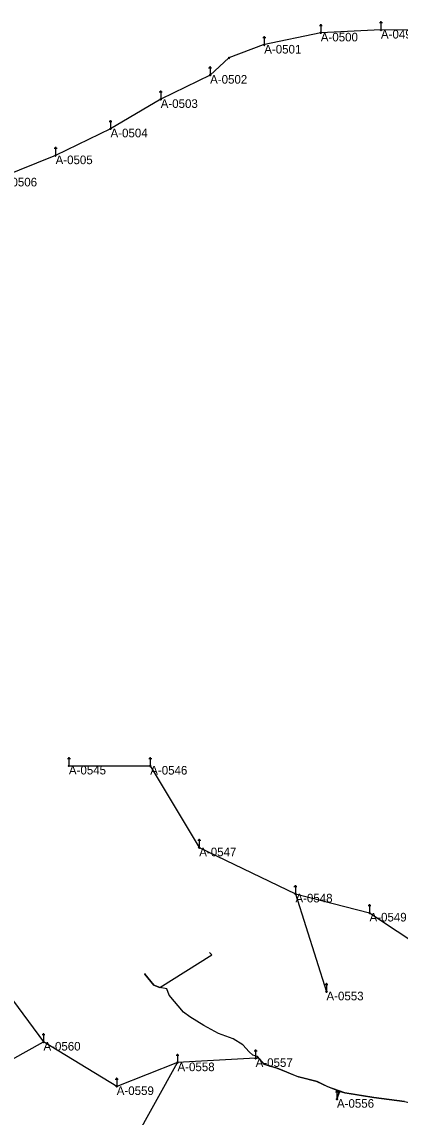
# Model space of a CAD drawing. Extents: x -729889 to -691139, y -995431 to -974354.
# Drawn here: x -725591.1 to -725459.3, y -977808.4 to -977426.9 of the extents above; entities that cross this region are included whole.
import ezdxf

# ---------------------------------------------------------------- set-up
doc = ezdxf.new("R2010")
doc.units = 0
for name, color, linetype in [('Atributy', 7, 'Continuous'), ('Kabel napájecí ze systému VO', 7, 'Continuous'), ('Kabelové vedení VO', 7, 'Continuous'), ('Spojka kabelová', 7, 'Continuous'), ('Světelný bod na stožáru sadovém', 7, 'Continuous')]:
    doc.layers.add(name, color=color, linetype=linetype)

# ---------------------------------------------------------------- blocks, each defined once
blk = doc.blocks.new('6.571')
at = {"layer": 'Světelný bod na stožáru sadovém'}
for p, q in [((-0.51, 2.54), (0.51, 2.54)), ((0, 2.54), (0, 0.2))]:
    blk.add_line(p, q, dxfattribs=at)
for points in [[(0.25, 2.54), (0.25, 2.56), (0.25, 2.58), (0.24, 2.6), (0.24, 2.62), (0.23, 2.64), (0.22, 2.66), (0.21, 2.69), (0.19, 2.7), (0.18, 2.72), (0.16, 2.73), (0.15, 2.75), (0.13, 2.76), (0.11, 2.77), (0.09, 2.78), (0.07, 2.78), (0.05, 2.79), (0.02, 2.79), (0, 2.79), (-0.02, 2.79), (-0.05, 2.79), (-0.07, 2.78), (-0.09, 2.78), (-0.11, 2.77), (-0.13, 2.76), (-0.15, 2.75), (-0.16, 2.73), (-0.18, 2.72), (-0.19, 2.7), (-0.21, 2.69), (-0.22, 2.66), (-0.23, 2.64), (-0.24, 2.62), (-0.24, 2.6), (-0.25, 2.58), (-0.25, 2.56), (-0.25, 2.54)], [(-0.2, 0), (-0.17, -0.1), (-0.08, -0.18), (0.04, -0.19), (0.13, -0.14), (0.19, -0.05), (0.18, 0.07), (0.12, 0.15), (0.02, 0.19), (-0.09, 0.17), (-0.17, 0.09), (-0.18, -0.01), (-0.15, -0.1), (-0.06, -0.17), (0.04, -0.17), (0.12, -0.12), (0.17, -0.03), (0.16, 0.08), (0.1, 0.14), (0.01, 0.17), (-0.09, 0.14), (-0.15, 0.07), (-0.16, -0.01), (-0.12, -0.1), (-0.04, -0.15), (0.04, -0.15), (0.12, -0.1), (0.15, -0.01), (0.14, 0.07), (0.08, 0.13), (-0.01, 0.15), (-0.09, 0.12), (-0.13, 0.06), (-0.14, -0.02), (-0.1, -0.1), (-0.03, -0.13), (0.04, -0.13), (0.11, -0.08), (0.13, 0), (0.12, 0.07), (0.06, 0.12), (-0.02, 0.13), (-0.08, 0.1), (-0.12, 0.05), (-0.12, -0.03), (-0.08, -0.09), (-0.02, -0.11), (0.05, -0.11), (0.1, -0.06), (0.11, 0.01), (0.1, 0.06), (0.05, 0.11), (-0.02, 0.11), (-0.07, 0.09), (-0.1, 0.04), (-0.1, -0.03), (-0.06, -0.08), (-0.02, -0.1), (0.05, -0.08), (0.09, -0.04), (0.1, 0.01), (0.08, 0.06), (0.03, 0.09), (-0.02, 0.09), (-0.06, 0.07), (-0.08, 0.02), (-0.08, -0.03), (-0.05, -0.06), (-0.01, -0.08), (0.04, -0.06), (0.07, -0.03), (0.07, 0.01), (0.06, 0.05), (0.02, 0.07), (-0.02, 0.07), (-0.05, 0.05), (-0.07, 0.02), (-0.06, -0.03), (-0.04, -0.05), (0, -0.06), (0.04, -0.04), (0.05, -0.02), (0.06, 0.01), (0.04, 0.04), (0.01, 0.05), (-0.02, 0.05), (-0.04, 0.04), (-0.05, 0.01), (-0.04, -0.02), (-0.02, -0.03), (0.01, -0.04), (0.03, -0.03), (0.04, -0.01), (0.04, 0.01), (0.02, 0.03), (0.01, 0.04), (-0.01, 0.03), (-0.02, 0.02), (-0.03, 0.01), (-0.02, -0.01), (-0.01, -0.02)], [(-0.01, -0.02), (0.01, -0.02), (0.01, -0.01), (0.02, 0), (0.02, 0.01), (0.01, 0.02), (0, 0.02), (-0.01, 0.01), (-0.01, 0.01), (-0.01, 0.01)]]:
    blk.add_lwpolyline(points, dxfattribs=at)
blk.add_circle((0, 0), 0.203, dxfattribs=at)
blk = doc.blocks.new('4.0200_BB')
at = {"layer": 'Spojka kabelová'}
blk.add_lwpolyline([(-0.02, 0.01), (-0.02, 0.17), (-0.1, 0.17), (-0.1, 0.21), (-0.02, 0.21), (-0.02, 0.28), (0.02, 0.28), (0.02, 0.21), (0.11, 0.21), (0.11, 0.17), (0.02, 0.17), (0.02, 0.01)], close=True, dxfattribs=at)
for radius in [0.15, 0.0945]:
    blk.add_circle((0, -0.13), radius, dxfattribs=at)

msp = doc.modelspace()

# ---------------------------------------------------------------- linework, layer by layer
at = {"layer": 'Kabel napájecí ze systému VO'}
for points in [[(-725548.15, -977758.36), (-725548.27, -977758.56), (-725545.1, -977762.41), (-725543.07, -977763.16), (-725524.88, -977751.79), (-725525.78, -977751.08)], [(-725457.8, -977802.91), (-725468.45, -977801.52), (-725478.54, -977799.9), (-725484.47, -977797.77), (-725488.21, -977795.98), (-725495.24, -977794.21), (-725501.53, -977791.51), (-725506.66, -977789.93), (-725509.04, -977787.25), (-725510.58, -977786.74), (-725511.92, -977785.63), (-725514.13, -977783.15), (-725517.54, -977781.11), (-725522.57, -977779.26), (-725527.75, -977776.47), (-725532.59, -977773.41), (-725534.79, -977771.84), (-725539.83, -977765.9), (-725540.63, -977763.69), (-725543.07, -977763.16), (-725545.1, -977762.41), (-725548.27, -977758.56), (-725548.15, -977758.36)]]:
    msp.add_lwpolyline(points, dxfattribs=at)
at = {"layer": 'Kabelové vedení VO'}
for p, q in [((-725486.95, -977430.69), (-725507.02, -977434.9)), ((-725466, -977429.71), (-725486.95, -977430.69)), ((-725444.44, -977429.86), (-725466, -977429.71)), ((-725525.51, -977445.41), (-725542.73, -977453.86)), ((-725542.73, -977453.86), (-725560.21, -977464.1)), ((-725560.21, -977464.1), (-725579.35, -977473.45)), ((-725579.35, -977473.45), (-725598.73, -977481.2)), ((-725574.71, -977686), (-725546.38, -977686.05)), ((-725546.38, -977686.05), (-725529.3, -977714.5)), ((-725529.3, -977714.5), (-725495.79, -977730.57)), ((-725495.79, -977730.57), (-725484.98, -977764.67)), ((-725495.79, -977730.57), (-725469.98, -977737.21)), ((-725469.98, -977737.21), (-725447.77, -977751.93)), ((-725609.81, -977746.65), (-725583.57, -977782.17)), ((-725610.39, -977797.01), (-725583.57, -977782.17)), ((-725558.05, -977797.64), (-725583.57, -977782.17)), ((-725536.88, -977789.35), (-725558.05, -977797.64)), ((-725555.35, -977822.68), (-725536.88, -977789.35)), ((-725509.65, -977787.86), (-725536.88, -977789.35))]:
    msp.add_line(p, q, dxfattribs=at)
for points in [[(-725507.02, -977434.9), (-725518.94, -977439.46), (-725525.51, -977445.41)], [(-725481.32, -977802.08), (-725480.56, -977799.68), (-725480.72, -977799.32), (-725484.46, -977797.86), (-725488.24, -977796.1), (-725494.6, -977794.5), (-725502.09, -977791.38), (-725506.72, -977790), (-725508.68, -977787.87), (-725509.19, -977787.78), (-725509.65, -977787.86)], [(-725443.89, -977804.51), (-725444.69, -977804.65), (-725450.67, -977804.6), (-725457.77, -977802.98), (-725468.49, -977801.59), (-725478.52, -977800.01), (-725480.09, -977799.61), (-725480.56, -977799.76), (-725481.32, -977802.08)]]:
    msp.add_lwpolyline(points, dxfattribs=at)

# ---------------------------------------------------------------- block references
at = {"layer": 'Spojka kabelová'}
msp.add_blockref('4.0200_BB', (-725518.94, -977439.46), dxfattribs=at)
at = {"layer": 'Světelný bod na stožáru sadovém', "xscale": 1.0016949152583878, "yscale": 1.0016949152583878}
for p in [(-725486.95, -977430.69), (-725466, -977429.71), (-725506.66, -977434.92), (-725525.51, -977445.41), (-725542.73, -977453.86), (-725560.21, -977464.1), (-725579.35, -977473.45), (-725574.71, -977686), (-725546.38, -977686.05), (-725529.3, -977714.5), (-725495.79, -977730.57), (-725469.98, -977737.21), (-725484.98, -977764.67), (-725583.57, -977782.17), (-725536.88, -977789.35), (-725509.65, -977787.86), (-725558.05, -977797.64), (-725481.32, -977802.08)]:
    msp.add_blockref('6.571', p, dxfattribs=at)

# ---------------------------------------------------------------- texts
at = {"layer": 'Atributy'}
for s, p in [('A-0500', (-725486.95, -977433.7)), ('A-0499', (-725466, -977432.72)), ('A-0501', (-725506.66, -977437.93)), ('A-0502', (-725525.51, -977448.42)), ('A-0503', (-725542.73, -977456.87)), ('A-0504', (-725560.21, -977467.11)), ('A-0505', (-725579.35, -977476.46)), ('A-0506', (-725598.73, -977484.21)), ('A-0545', (-725574.71, -977689.01)), ('A-0546', (-725546.38, -977689.06)), ('A-0547', (-725529.3, -977717.51)), ('A-0548', (-725495.79, -977733.58)), ('A-0549', (-725469.98, -977740.22)), ('A-0553', (-725484.98, -977767.68)), ('A-0560', (-725583.57, -977785.18)), ('A-0558', (-725536.88, -977792.36)), ('A-0557', (-725509.65, -977790.87)), ('A-0559', (-725558.05, -977800.65)), ('A-0556', (-725481.32, -977805.09))]:
    msp.add_text(s, height=3, dxfattribs=at).set_placement(p)

doc.saveas('drawing.dxf')
